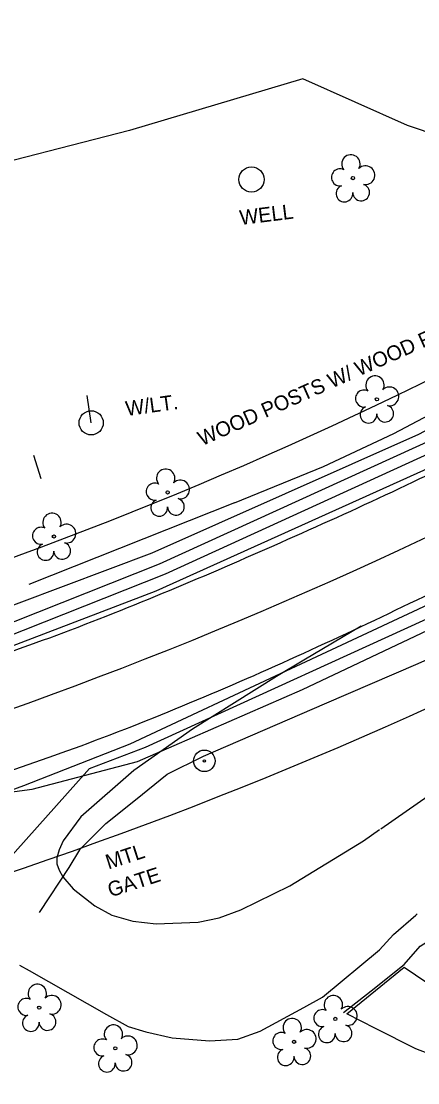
# Model space of a CAD drawing. Extents: x 1645945 to 2447332, y 713118 to 970361.
# Drawn here: x 1647317.1 to 1647397.4, y 969522.3 to 969737.2 of the extents above; entities that cross this region are included whole.
import ezdxf

# ---------------------------------------------------------------- set-up
doc = ezdxf.new("R2010")
doc.units = 0
for name, color, linetype in [('Exist Horizontal Alignment', 7, 'Continuous'), ('Exist Other Culture Area Outline', 7, 'Continuous'), ('Exist Other Culture Fence Line', 7, 'Continuous'), ('Exist Other Culture Fence Line Text', 7, 'Continuous'), ('Exist Other Culture Gate', 7, 'Continuous'), ('Exist Other Culture Gate Text', 7, 'Continuous'), ('Exist Other Culture Located Object CELL', 7, 'Continuous'), ('Exist Other Culture Sign CELL', 7, 'Continuous'), ('Exist Other Culture Well CELL', 7, 'Continuous'), ('Exist Other Culture Well Text', 7, 'Continuous'), ('Exist Right of Way Line', 7, 'Continuous'), ('Exist Roads EOP', 7, 'Continuous'), ('Exist Roads Soil', 7, 'Continuous'), ('Exist Utilities Power Pole CELL', 7, 'Continuous'), ('Exist Utilities Power Pole Text', 7, 'Continuous'), ('Exist Utilities Sanitary Sewer Forced Main SUE LOS B', 7, 'Continuous'), ('Exist Utilities Telephone UG Cable SUE LOS C', 7, 'Continuous'), ('Exist Utilities Telephone UG Conduit SUE LOS B', 7, 'Continuous'), ('Exist Utilities Telephone UG FO SUE LOS C', 7, 'Continuous'), ('Exist Vegetation Tree CELL', 7, 'Continuous'), ('Exist Vegetation Woods Line', 7, 'Continuous')]:
    doc.layers.add(name, color=color, linetype=linetype)

msp = doc.modelspace()

# ---------------------------------------------------------------- linework, layer by layer
at = {"layer": 'Exist Horizontal Alignment'}
msp.add_arc((1647013.36, 970445.89), 900, 278.18107, 298.87121, dxfattribs=at)
at = {"layer": 'Exist Other Culture Area Outline'}
msp.add_lwpolyline([(1647411.84, 969523.84), (1647407.07, 969525.32), (1647396.98, 969529.18), (1647388.81, 969533.3), (1647383.02, 969536.31), (1647394.64, 969545.72), (1647396.91, 969544.16), (1647400.94, 969541.47), (1647405.12, 969538.89)], dxfattribs=at)
at = {"layer": 'Exist Other Culture Fence Line'}
for p, q in [((1647360.31, 969639.7), (1647318.68, 969623.18)), ((1647328.92, 969569.45), (1647326.75, 969565.92))]:
    msp.add_line(p, q, dxfattribs=at)
for points in [[(1647378.48, 969599.04), (1647397.5, 969607.19), (1647419.7, 969617.12), (1647432.85, 969623.77), (1647446.7, 969631.34), (1647460.79, 969639.34), (1647468.57, 969643.81), (1647481.65, 969651.11), (1647495.44, 969658.93), (1647516.04, 969670.64), (1647542.37, 969686.67), (1647555.03, 969695.43), (1647566.23, 969704.89), (1647576.04, 969713.96), (1647601.68, 969736.14), (1647620.49, 969754.94)], [(1647360.31, 969639.7), (1647378.33, 969647.09), (1647392.53, 969653.79), (1647421.31, 969668.92), (1647442.47, 969680.24)], [(1647328.92, 969569.45), (1647334.21, 969574.83), (1647340.22, 969579.62), (1647346.68, 969584.83), (1647354.01, 969588.42), (1647378.48, 969599.04)], [(1647382.35, 969536.58), (1647387.97, 969540.94), (1647394.64, 969546.24), (1647397.88, 969549.96), (1647406.66, 969555.58)]]:
    msp.add_lwpolyline(points, dxfattribs=at)
at = {"layer": 'Exist Other Culture Gate'}
msp.add_line((1647326.9, 969566.08), (1647320.71, 969556.78), dxfattribs=at)
at = {"layer": 'Exist Other Culture Located Object CELL'}
for radius in [2.18, 0.24]:
    msp.add_circle((1647354.19, 969587.49), radius, dxfattribs=at)
at = {"layer": 'Exist Other Culture Sign CELL'}
msp.add_line((1647319.59, 969649.36), (1647321.05, 969644.67), dxfattribs=at)
at = {"layer": 'Exist Other Culture Well CELL'}
msp.add_circle((1647363.73, 969705.19), 2.56, dxfattribs=at)
at = {"layer": 'Exist Right of Way Line'}
for radius in [845, 905]:
    msp.add_arc((1647025.62, 970422.4), radius, 278.18107, 299.46236, dxfattribs=at)
at = {"layer": 'Exist Roads EOP'}
for points in [[(1647712.71, 969946.05), (1647689.83, 969906.56), (1647665.85, 969869.13), (1647637.34, 969829.12), (1647607.92, 969794.57), (1647574.53, 969760.72), (1647538.69, 969730.5), (1647499.85, 969702.79), (1647457.34, 969676.33), (1647411.66, 969651.37), (1647366.8, 969630.41), (1647321.37, 969611.83), (1647279.28, 969597.97), (1647224.82, 969583.15), (1647179.92, 969574.15), (1647132.17, 969565.53), (1647083.22, 969557.97), (1647036.22, 969550.58), (1646989.26, 969543.73)], [(1647731.3, 969935.45), (1647707.71, 969895.07), (1647684.27, 969857.13), (1647654.38, 969814.5), (1647624.46, 969779.25), (1647589.97, 969744.66), (1647553.5, 969714.01), (1647512.43, 969684.95), (1647469.3, 969658.19), (1647421.26, 969632.07), (1647375.68, 969609.9), (1647329.15, 969590.49), (1647286.02, 969576.26), (1647230.19, 969561.18), (1647183.04, 969552.75), (1647135.89, 969544.58), (1647086.4, 969536.99), (1647040.14, 969529.53), (1646992.05, 969522.32)]]:
    msp.add_spline(points, degree=3, dxfattribs=at)
at = {"layer": 'Exist Roads Soil'}
for points in [[(1647389.89, 969573.75), (1647409.76, 969587.55), (1647437.43, 969606.18), (1647459.13, 969620.72), (1647467.03, 969625.99), (1647476.84, 969632.04), (1647483.95, 969636.05), (1647493.34, 969640.91), (1647499.96, 969643.81), (1647508.28, 969647.15), (1647515.88, 969650.1), (1647523.28, 969652.1), (1647531.66, 969654.03), (1647535.94, 969654.81), (1647545.88, 969656.29), (1647551.02, 969656.8), (1647552.03, 969657.34), (1647553.18, 969658.4), (1647559.42, 969668.42)], [(1647385.95, 969614.74), (1647374.31, 969607.86)], [(1647374.31, 969607.86), (1647368.77, 969604.58), (1647351.77, 969593.92), (1647339.94, 969585.54), (1647329.15, 969576.18), (1647325.58, 969571.3), (1647324.79, 969569.45), (1647324.31, 969567.89), (1647324.32, 969566.62), (1647324.76, 969565.34), (1647325.56, 969563.98), (1647327.6, 969561.61), (1647332.01, 969558.17), (1647335.48, 969556.24), (1647339.68, 969555.02), (1647344.43, 969554.52), (1647352.96, 969554.83), (1647357.2, 969555.71), (1647361.55, 969557.34), (1647371.47, 969562.18), (1647386.4, 969571.33)], [(1647386.4, 969571.33), (1647389.67, 969573.6)], [(1647316.75, 969546.14), (1647318.75, 969545.08), (1647334.38, 969536.11), (1647338.75, 969533.74), (1647342.32, 969532.62), (1647347.69, 969531.42), (1647355.21, 969530.8), (1647360.96, 969531.14), (1647365.46, 969532.77), (1647374.35, 969537.53), (1647378.08, 969539.67), (1647389.63, 969549.25), (1647392.49, 969552.31), (1647397, 969556.28)], [(1647397, 969556.28), (1647397.3, 969556.55)]]:
    msp.add_lwpolyline(points, dxfattribs=at)
at = {"layer": 'Exist Utilities Power Pole CELL'}
for q in [(1647330.47, 969661.49), (1647331.27, 969655.93)]:
    msp.add_line((1647331.27, 969655.93), q, dxfattribs=at)
msp.add_circle((1647331.27, 969655.93), 2.45, dxfattribs=at)
at = {"layer": 'Exist Utilities Sanitary Sewer Forced Main SUE LOS B'}
msp.add_lwpolyline([(1647281.82, 969570.96), (1647301.43, 969576.57), (1647317.63, 969582.51), (1647339.14, 969590.95), (1647371.77, 969606.21), (1647423.35, 969630.3), (1647468.23, 969654.45), (1647489.07, 969666.65), (1647526.6, 969691.29), (1647564.25, 969719.63), (1647582.69, 969734.56), (1647601.35, 969752.36), (1647608.99, 969759.23), (1647621.71, 969772.62)], dxfattribs=at)
at = {"layer": 'Exist Utilities Telephone UG Cable SUE LOS C'}
for points in [[(1647301.18, 969607.49), (1647346.35, 969625.33), (1647402.72, 969651.12), (1647431.08, 969666.24), (1647439.41, 969670.62), (1647442.16, 969672.78), (1647445.5, 969676.48), (1647448.63, 969678.56), (1647474.06, 969693.41), (1647520.52, 969726.92), (1647556, 969754.87), (1647590.11, 969785.42), (1647617.35, 969813.54), (1647647.46, 969852.3), (1647702.67, 969945.18), (1647775.84, 970087.47)], [(1647299.74, 969604.87), (1647344.43, 969621.93), (1647402.05, 969647.91), (1647428.7, 969661.61), (1647441.47, 969668.79), (1647444.57, 969671.27), (1647446.47, 969673.44), (1647447.93, 969674.84), (1647451.1, 969676.98), (1647475.41, 969691.19), (1647501.84, 969708.82), (1647529.96, 969729.71), (1647548.6, 969744.41), (1647576.21, 969768.81), (1647599.16, 969791.2), (1647624.94, 969819.94), (1647649.96, 969852.56), (1647680.88, 969902.23), (1647705.82, 969944.72), (1647779.36, 970085.84)], [(1647294.11, 969544.68), (1647330.92, 969585.92), (1647342.26, 969590.26), (1647406.15, 969619.43), (1647450.3, 969642.78), (1647488.96, 969665.16), (1647521.25, 969685.99), (1647545.76, 969703.5), (1647563.98, 969716.93), (1647573.87, 969725.16), (1647593.32, 969742.95), (1647627.6, 969780.32), (1647655.82, 969815.07), (1647672.99, 969839.14), (1647691.44, 969867.28), (1647722.34, 969918.27), (1647755.1, 969977.16), (1647804.4, 970074.3)]]:
    msp.add_lwpolyline(points, dxfattribs=at)
at = {"layer": 'Exist Utilities Telephone UG Conduit SUE LOS B'}
msp.add_lwpolyline([(1647288.65, 969579.3), (1647300.87, 969579.36), (1647319.33, 969581.75), (1647340.65, 969587.35), (1647374.06, 969601.91), (1647427.36, 969627.15), (1647470.88, 969652.02), (1647490.61, 969664.32), (1647528.7, 969688.64), (1647565.5, 969715.45)], dxfattribs=at)
at = {"layer": 'Exist Utilities Telephone UG FO SUE LOS C'}
for points in [[(1647289.7, 969609.34), (1647343.59, 969629.58), (1647397.62, 969653.63), (1647450.96, 969681.88), (1647471.14, 969694.21), (1647529.28, 969736.65), (1647578.89, 969778.78), (1647616.07, 969816.36), (1647645.02, 969855.2), (1647696.33, 969943.83), (1647771.33, 970089.55)], [(1647291.19, 969605.96), (1647345.09, 969627.35), (1647401.66, 969653.17), (1647434.03, 969670.53), (1647438.26, 969672.06), (1647445.18, 969672.38), (1647450.09, 969673.09), (1647455.34, 969675.46), (1647473.43, 969686.09), (1647508.86, 969709.29), (1647532.76, 969727.04), (1647549.35, 969740.28), (1647575.78, 969764.21), (1647609.03, 969797.83), (1647638.13, 969832.64), (1647665.39, 969871.17), (1647698.7, 969925.68), (1647740.76, 970001.75), (1647782.56, 970084.37)]]:
    msp.add_lwpolyline(points, dxfattribs=at)
at = {"layer": 'Exist Vegetation Tree CELL'}
for p, q in [((1647384.25, 969705.47), (1647384.25, 969705.47)), ((1647389.12, 969660.69), (1647389.12, 969660.69)), ((1647346.75, 969641.84), (1647346.75, 969641.84)), ((1647323.73, 969632.91), (1647323.73, 969632.91)), ((1647320.75, 969537.53), (1647320.75, 969537.53)), ((1647380.69, 969535.25), (1647380.69, 969535.25)), ((1647372.36, 969530.61), (1647372.36, 969530.61)), ((1647336.16, 969529.3), (1647336.16, 969529.3))]:
    msp.add_line(p, q, dxfattribs=at)
for centre in [(1647384.25, 969705.47), (1647389.12, 969660.69), (1647346.75, 969641.84), (1647323.73, 969632.91), (1647320.75, 969537.53), (1647380.69, 969535.25), (1647372.36, 969530.61), (1647336.16, 969529.3)]:
    msp.add_circle(centre, 0.326, dxfattribs=at)
for centre, radius, start, end in [((1647383.86, 969708.34), 1.86, 330.1651, 219.7134), ((1647381.64, 969705.62), 1.73, 62.6636, 279.3457), ((1647386.8, 969706.06), 1.9, 257.1011, 134.1999), ((1647382.54, 969702.35), 1.69, 111.5671, 6.231), ((1647385.92, 969702.57), 1.7, 181.2822, 74.56), ((1647388.73, 969663.56), 1.86, 330.1651, 219.7134), ((1647386.51, 969660.84), 1.73, 62.6636, 279.3457), ((1647391.66, 969661.28), 1.9, 257.1011, 134.1999), ((1647390.79, 969657.79), 1.7, 181.2822, 74.56), ((1647387.41, 969657.57), 1.69, 111.5671, 6.231), ((1647346.36, 969644.71), 1.86, 330.1651, 219.7134), ((1647349.29, 969642.43), 1.9, 257.1011, 134.1999), ((1647344.14, 969641.99), 1.73, 62.6636, 279.3457), ((1647345.04, 969638.72), 1.69, 111.5671, 6.231), ((1647348.42, 969638.94), 1.7, 181.2822, 74.56), ((1647323.34, 969635.78), 1.86, 330.1651, 219.7134), ((1647321.12, 969633.06), 1.73, 62.6636, 279.3457), ((1647326.28, 969633.49), 1.9, 257.1011, 134.1999), ((1647322.03, 969629.78), 1.69, 111.5671, 6.231), ((1647325.4, 969630.01), 1.7, 181.2822, 74.56), ((1647320.37, 969540.4), 1.86, 330.1651, 219.7134), ((1647318.15, 969537.68), 1.73, 62.6636, 279.3457), ((1647323.3, 969538.11), 1.9, 257.1011, 134.1999), ((1647380.3, 969538.12), 1.86, 330.1651, 219.7134), ((1647378.08, 969535.4), 1.73, 62.6636, 279.3457), ((1647383.24, 969535.84), 1.9, 257.1011, 134.1999), ((1647319.05, 969534.41), 1.69, 111.5671, 6.231), ((1647322.43, 969534.63), 1.7, 181.2822, 74.56), ((1647371.98, 969533.49), 1.86, 330.1651, 219.7134), ((1647335.77, 969532.17), 1.86, 330.1651, 219.7134), ((1647369.76, 969530.77), 1.73, 62.6636, 279.3457), ((1647374.91, 969531.2), 1.9, 257.1011, 134.1999), ((1647378.98, 969532.13), 1.69, 111.5671, 6.231), ((1647382.36, 969532.35), 1.7, 181.2822, 74.56), ((1647333.55, 969529.45), 1.73, 62.6636, 279.3457), ((1647338.71, 969529.89), 1.9, 257.1011, 134.1999), ((1647370.66, 969527.49), 1.69, 111.5671, 6.231), ((1647374.03, 969527.71), 1.7, 181.2822, 74.56), ((1647334.45, 969526.18), 1.69, 111.5671, 6.231), ((1647337.83, 969526.4), 1.7, 181.2822, 74.56)]:
    msp.add_arc(centre, radius, start, end, dxfattribs=at)
at = {"layer": 'Exist Vegetation Woods Line'}
msp.add_lwpolyline([(1647517.03, 969744.5), (1647495.35, 969729.99), (1647471.19, 969716.25), (1647460.39, 969710.38), (1647431.64, 969709.61), (1647415.55, 969712.4), (1647401.93, 969713.9), (1647395.29, 969716.09), (1647374.09, 969725.56), (1647339.04, 969715.08), (1647303.79, 969706.09), (1647302.25, 969707.44), (1647299.84, 969713.9), (1647295.54, 969715.64), (1647292.3, 969714.45), (1647288.08, 969706.3), (1647285.4, 969706.33), (1647270.06, 969708.07), (1647265.52, 969709.48), (1647237.13, 969734.31), (1647228.98, 969743.77)], dxfattribs=at)

# ---------------------------------------------------------------- texts
at = {"layer": 'Exist Other Culture Fence Line Text'}
msp.add_text('WOOD POSTS W/ WOOD RAIL', height=3, rotation=23.9539, dxfattribs=at).set_placement((1647353.71, 969651.19))
at = {"layer": 'Exist Other Culture Gate Text'}
for s, p in [('MTL', (1647334.76, 969565.49)), ('GATE', (1647335.18, 969559.85))]:
    msp.add_text(s, height=3, rotation=17.887, dxfattribs=at).set_placement(p)
at = {"layer": 'Exist Other Culture Well Text'}
msp.add_text('WELL', height=3, rotation=7.0134, dxfattribs=at).set_placement((1647361.51, 969695.96))
at = {"layer": 'Exist Utilities Power Pole Text'}
msp.add_text('W/LT.', height=3, rotation=7.7882, dxfattribs=at).set_placement((1647338.44, 969657.3))

doc.saveas('drawing.dxf')
